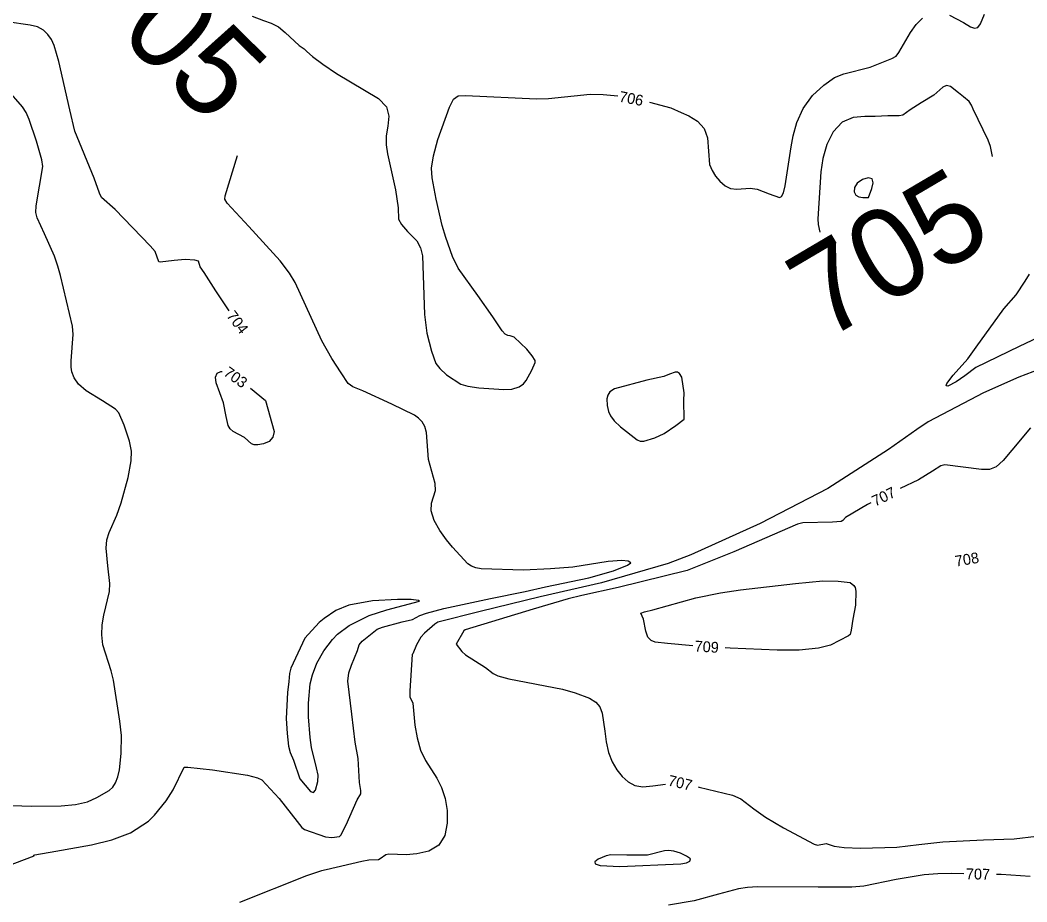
# Model space of a CAD drawing. Extents: x -291892836 to 2945206, y -477993085 to 1832792.
# Drawn here: x 1852737.2 to 1853109.9, y 543885.5 to 544211.9 of the extents above; entities that cross this region are included whole.
import ezdxf

# ---------------------------------------------------------------- set-up
doc = ezdxf.new("R2010")
doc.units = 0
for name, color, linetype in [('DT_X_Contour_Minor', 7, 'Continuous'), ('DT_X_Terrain_Ground_Line', 7, 'Continuous'), ('Level 19', 7, 'Continuous')]:
    doc.layers.add(name, color=color, linetype=linetype)

msp = doc.modelspace()

# ---------------------------------------------------------------- linework, layer by layer
at = {"layer": 'DT_X_Contour_Minor'}
for points in [[(1853081.32, 544213.75), (1853086.51, 544210.99), (1853089.13, 544209.42), (1853090.5, 544208.94), (1853091.76, 544209.2), (1853092.83, 544210.45), (1853094.24, 544214.1)], [(1852814.6, 544104.26), (1852809.64, 544111.65), (1852805.39, 544118.44), (1852803.82, 544120.6), (1852803.22, 544122.59), (1852801.84, 544122.98), (1852798.27, 544123.22), (1852794.23, 544122.86), (1852789.04, 544122.25), (1852788.6, 544122.45), (1852787.26, 544126.16), (1852785.39, 544128.35), (1852772.45, 544141.76), (1852767.38, 544146.19), (1852766.54, 544147.78), (1852764.59, 544153.4), (1852757.47, 544170.78), (1852755.59, 544178.62), (1852751.55, 544196.61), (1852749.78, 544202.53), (1852748.8, 544204.66), (1852747.5, 544206.59), (1852745.8, 544208.19), (1852743.64, 544209.35), (1852740.98, 544210.01), (1852732.44, 544211.22)], [(1852823.09, 544213.36), (1852827.35, 544211.79), (1852830.1, 544210.79), (1852832.87, 544209.33), (1852835.38, 544207.33), (1852840.48, 544202.47), (1852842.34, 544201.26), (1852843.32, 544200.22), (1852845.48, 544198.36), (1852849.28, 544195.55), (1852854.28, 544192.17), (1852869.83, 544182.87), (1852872.81, 544179.82), (1852873.76, 544176.33), (1852873.4, 544172.62), (1852872.79, 544169.02), (1852872.74, 544165.72), (1852873.25, 544162.36), (1852876.13, 544148.99), (1852877.14, 544142.38), (1852877.34, 544138.22), (1852878.38, 544136.21), (1852880.67, 544133.67)], [(1852970.25, 544181.51), (1852978.1, 544179.42), (1852982, 544177.73), (1852984.82, 544176.41), (1852987.97, 544174.43), (1852990.49, 544171.73), (1852991.65, 544168.31), (1852992.44, 544158.43), (1852993.37, 544156.18), (1852994.68, 544154.16), (1852996.3, 544152.2), (1852998.18, 544150.53), (1853000.27, 544149.51), (1853002.55, 544149.33), (1853007.52, 544149.68), (1853010.11, 544149.24), (1853014.51, 544147.6), (1853018.39, 544146.18), (1853019.14, 544146.55), (1853019.84, 544147.92), (1853020.44, 544150.55), (1853022.68, 544164.94), (1853023.43, 544168.99), (1853024.76, 544173.99), (1853027.08, 544179.2), (1853030.58, 544183.94), (1853034.72, 544187.84), (1853038.77, 544190.59), (1853042.19, 544192.05), (1853051.88, 544194.41), (1853060.01, 544197.65), (1853061.56, 544198.49), (1853062.59, 544199.93), (1853066.8, 544207.28), (1853068.94, 544210.27), (1853071.26, 544212.65)], [(1852774.57, 543940.37), (1852774.74, 543947), (1852774.12, 543952.31), (1852771.81, 543967.5), (1852770.97, 543970.99), (1852767.87, 543980.64), (1852767.51, 543984.27), (1852767.63, 543988.01), (1852768.15, 543991.55), (1852770.33, 544000.35), (1852770.43, 544003.35), (1852769.71, 544009.82), (1852769.04, 544016.42), (1852769.28, 544019.45), (1852770.15, 544022.21), (1852773.07, 544028.67), (1852774.66, 544033.17), (1852777.22, 544042.58), (1852778.29, 544048.76), (1852778.4, 544052.31), (1852777.67, 544056), (1852775.77, 544061.93), (1852773.73, 544066.48), (1852772.48, 544067.81), (1852767.72, 544070.93), (1852761.71, 544074.7), (1852758.79, 544077.12), (1852757.24, 544079.47), (1852756.39, 544081.7), (1852756.09, 544083.41), (1852756.05, 544085.74), (1852756.89, 544095.5), (1852756.59, 544098.53), (1852752.12, 544117.38), (1852751.19, 544120.74), (1852749.9, 544124.46), (1852746.23, 544132.77), (1852743.47, 544138.64), (1852742.99, 544140.63), (1852743.13, 544143.14), (1852745.56, 544157.67), (1852745.27, 544160.19), (1852743.28, 544167.09), (1852740.54, 544175.11), (1852739.42, 544177.66), (1852738.04, 544179.76), (1852732.32, 544186.41)], [(1852880.67, 544133.67), (1852884.1, 544130.11), (1852885.46, 544127.63), (1852886.17, 544124.56), (1852886.43, 544117.37), (1852886.96, 544102.95), (1852887.74, 544095.94), (1852889.47, 544089.37), (1852891.14, 544084.71), (1852892.58, 544082.9), (1852895.01, 544080.54), (1852900.38, 544077.08), (1852902.91, 544076.4), (1852907.06, 544075.79), (1852916.29, 544075.16), (1852919.21, 544075.3), (1852921.96, 544076.11), (1852923.61, 544077.25), (1852924.54, 544078.41), (1852926.72, 544082.24), (1852927.94, 544085.12), (1852927.9, 544085.84), (1852926.8, 544087.56), (1852924.75, 544090.1), (1852920.13, 544094.48), (1852918.6, 544094.97), (1852917.81, 544095.15), (1852916.84, 544095.67), (1852915.62, 544096.88), (1852912.18, 544102.07), (1852906.72, 544109.96), (1852899.37, 544120.06), (1852897.32, 544124.37), (1852894.77, 544131.38), (1852893.43, 544135.9), (1852891.25, 544145.63), (1852889.74, 544153.52), (1852889.56, 544157.08), (1852890.21, 544161.62), (1852891.87, 544167.72), (1852896.12, 544179.6), (1852897.67, 544182.66), (1852899.36, 544183.83), (1852902.1, 544183.95), (1852928.42, 544182.68), (1852932.78, 544182.84), (1852948.24, 544184.44), (1852953.12, 544184.33), (1852958.47, 544183.8)], [(1853097.26, 544161.35), (1853096.44, 544165.12), (1853095.56, 544167.41), (1853090.02, 544178.94), (1853089.47, 544180.4), (1853088.52, 544181.76), (1853086.51, 544183.42), (1853084.58, 544184.94), (1853081.73, 544187.3), (1853080.22, 544187.73), (1853078.81, 544187.09), (1853075.49, 544184.05), (1853070.78, 544181.21), (1853066.73, 544178.64), (1853064.01, 544176.74), (1853062.7, 544176.47), (1853058.47, 544176.41), (1853053.79, 544176.14), (1853049.95, 544176.2), (1853045.6, 544175.78), (1853041.5, 544174.07), (1853038.26, 544170.56), (1853035.93, 544165.8), (1853034.43, 544160.63), (1853033.66, 544155.76), (1853032.53, 544138.33), (1853032.66, 544136.17), (1853033.34, 544133.36)], [(1852858.94, 543970.2), (1852859.95, 543973.07), (1852862.11, 543978.5), (1852862.78, 543980.61), (1852863.81, 543981.96), (1852869.42, 543986.36), (1852871.36, 543987.11), (1852878.65, 543989.07), (1852882.43, 543990.02), (1852885.25, 543991.47), (1852887.64, 543992.37), (1852894.07, 543994.08), (1852911.32, 543997.8), (1852924.25, 544000.41), (1852931.72, 544002.13), (1852947.75, 544005.4), (1852956.92, 544007.98), (1852962.07, 544010.05), (1852963.3, 544011), (1852962.37, 544011.56), (1852959.97, 544011.77), (1852954.88, 544011.49), (1852941.79, 544009.4), (1852933.53, 544008.74), (1852923.56, 544008.25), (1852907.94, 544008.73), (1852905.96, 544009.15), (1852904.27, 544009.78), (1852903.02, 544010.64), (1852897.28, 544016.79), (1852895.02, 544019.51), (1852892.62, 544022.96), (1852890.56, 544026.69), (1852889.43, 544030.18), (1852889.55, 544033), (1852890.97, 544037.73), (1852890.84, 544040.28), (1852888.41, 544049.22), (1852887.66, 544059.27), (1852886.99, 544061.46), (1852886.01, 544063.22), (1852884.76, 544064.58), (1852883.24, 544065.66), (1852874.84, 544069.75), (1852864.11, 544074.63), (1852860.36, 544076.13), (1852858.68, 544077.36), (1852856.12, 544081.28), (1852852.62, 544086.57), (1852848.95, 544093.2), (1852839.04, 544114.74), (1852837, 544118.17), (1852833.47, 544122.75), (1852821.83, 544135.49), (1852813.92, 544144.12), (1852812.97, 544145.54), (1852813.17, 544146.78), (1852817.69, 544161.73)], [(1853051.34, 544146.23), (1853052.59, 544149.53), (1853053.04, 544151.58), (1853052.69, 544153.08), (1853051.16, 544153.45), (1853049.04, 544152.84), (1853047.13, 544151.56), (1853046.1, 544149.95), (1853045.96, 544148.34), (1853046.58, 544147.07), (1853047.78, 544146.4), (1853049.19, 544146.19), (1853051.34, 544146.23)], [(1853123.05, 544098.64), (1853107.12, 544091), (1853091.04, 544083.28), (1853086.94, 544080.22), (1853083.76, 544077.94), (1853080.64, 544076.41), (1853080.05, 544076.47), (1853080.33, 544077.33), (1853082.69, 544080.47), (1853088.03, 544086.52), (1853091.15, 544090.85), (1853101.44, 544104.94), (1853105.94, 544110.12), (1853109.31, 544115.26), (1853110.87, 544117.85)], [(1853117.29, 544083.7), (1853107.02, 544079.68), (1853093.89, 544073.91), (1853088.95, 544071.25), (1853073.4, 544063.18), (1853069.16, 544060.37), (1853058.77, 544052.91), (1853036.28, 544038.46), (1853011.26, 544025.5), (1852985.52, 544013.92), (1852977.12, 544010.66), (1852952.44, 544003.58), (1852929.71, 543998.4), (1852907.57, 543992.92), (1852891.89, 543988.99), (1852890.8, 543988.3), (1852886.96, 543984.97), (1852885.53, 543983.41), (1852883.94, 543980.55), (1852882.61, 543977.29), (1852882.36, 543977.07), (1852881.48, 543963.63), (1852881.51, 543961.33), (1852882.6, 543958.97), (1852883.39, 543950.92), (1852884.19, 543946.17), (1852885.46, 543941.56), (1852887.27, 543937.76), (1852891.44, 543931.31), (1852893.2, 543927.76), (1852894.52, 543923.77), (1852895.29, 543919.33), (1852895.37, 543914.56), (1852894.46, 543910.03), (1852892.22, 543906.41), (1852888.52, 543904.21), (1852884.14, 543903.18), (1852880.09, 543902.91), (1852873.74, 543903.16), (1852872.57, 543902.81), (1852870.53, 543901.41), (1852869.94, 543901), (1852866.27, 543900.84), (1852863.74, 543900.41), (1852850.51, 543897.29), (1852848.82, 543897), (1852843.21, 543895.13), (1852818.44, 543885.17)], [(1852822.48, 544075.68), (1852828.01, 544071.08), (1852831.23, 544059.54), (1852830.83, 544057.46), (1852829.35, 544055.94), (1852827.27, 544055), (1852825.26, 544054.59), (1852823.83, 544054.65), (1852822.93, 544055.04), (1852820.29, 544057.31), (1852816.03, 544059.54), (1852815, 544060.58), (1852814.29, 544061.84), (1852813.47, 544065.15), (1852812.5, 544070.17), (1852809.77, 544077.65), (1852809.57, 544079.72), (1852810.15, 544081.18), (1852811.52, 544081.83), (1852812.07, 544081.74)], [(1852983.04, 544064.15), (1852982.99, 544071.12), (1852983.06, 544073.87), (1852982.25, 544079.69), (1852981.32, 544081.08), (1852980.61, 544081.5), (1852979.74, 544081.6), (1852977.66, 544080.85), (1852975.51, 544079.89), (1852969.18, 544078.55), (1852957.26, 544075.35), (1852955.53, 544074.23), (1852954.76, 544073.08), (1852954.41, 544071.62), (1852954.53, 544069.22), (1852955.1, 544066.93), (1852955.77, 544065.37), (1852957.2, 544063.48), (1852959.43, 544061.31), (1852965.62, 544056.47), (1852966.83, 544056.01), (1852968.1, 544056.03), (1852972.23, 544057.28), (1852975.68, 544058.8), (1852980.02, 544061.8), (1852983.04, 544064.15)], [(1853111.25, 544060.89), (1853104.42, 544052.64), (1853101.16, 544048.79), (1853098.54, 544046.48), (1853096.1, 544045.55), (1853093.2, 544045.53), (1853079.62, 544047.24), (1853078.14, 544046.9), (1853075.05, 544044.89), (1853069.86, 544041.74), (1853063.04, 544038.44)], [(1853052.23, 544033.23), (1853050.97, 544032.61), (1853042.76, 544027.79), (1853041.82, 544026.61), (1853041.17, 544026.28), (1853038.04, 544026.07), (1853026.97, 544025.79), (1853025, 544025.22), (1853001.51, 544015.1), (1852984.15, 544008.11), (1852958.64, 544001.89), (1852945.12, 543998.83), (1852940.16, 543997.62), (1852927.12, 543993.82), (1852901.92, 543986.15), (1852901.46, 543985.81), (1852898.64, 543980.9), (1852900.71, 543978.2), (1852902.13, 543976.97), (1852909.51, 543972.28), (1852912.37, 543970.01), (1852914.08, 543969.19), (1852918.15, 543968.08), (1852938.03, 543964.15), (1852942.66, 543962.89), (1852948.03, 543960.89), (1852950.3, 543959.44), (1852951.82, 543957.61), (1852952.72, 543955.27), (1852953.64, 543948.65), (1852954.15, 543944.66), (1852954.99, 543940.75), (1852956.35, 543937.27), (1852958.11, 543934.28), (1852960.14, 543931.81), (1852962.31, 543929.87), (1852964.8, 543928.58), (1852967.8, 543928.08), (1852971.43, 543928.37), (1852976.16, 543929.06)], [(1852986.23, 543980.3), (1852976.85, 543981.15), (1852972.31, 543981.65), (1852970.82, 543982.24), (1852969.6, 543983.51), (1852968.86, 543985.61), (1852968.05, 543990.14), (1852967, 543992.37), (1852968.43, 543992.82), (1852971.5, 543993.53), (1852987.36, 543998), (1852996.5, 543999.86), (1853003.95, 544001.01), (1853024.28, 544003.32), (1853034.42, 544004.27), (1853040.03, 544004.24), (1853044.58, 544003.73), (1853045.92, 544002.59), (1853046.32, 544001.89), (1853046.58, 544000.5), (1853046.53, 543995.28), (1853045.54, 543990.13), (1853044.85, 543986.09), (1853044.56, 543984.44), (1853043.95, 543983.96), (1853037.18, 543980.44), (1853032.77, 543979.32), (1853025.68, 543978.66), (1853017.47, 543978.58), (1853000.12, 543979.32), (1852998.2, 543979.44)], [(1852836.55, 543943.16), (1852837.17, 543940.7), (1852838.45, 543937.86), (1852840.74, 543931), (1852844.77, 543926.26), (1852845.78, 543925.96), (1852846.56, 543926.8), (1852847.43, 543930.05), (1852847.59, 543932.31), (1852846.99, 543935.07), (1852845.08, 543942.55), (1852844.56, 543946.35), (1852844.01, 543953.95), (1852843.97, 543959.01), (1852844.64, 543966.16), (1852845.42, 543969.51), (1852847.08, 543973.79), (1852849.71, 543978.45), (1852852.92, 543982.6), (1852854.7, 543984.56), (1852859.05, 543987.83), (1852866.49, 543991.44), (1852872.99, 543993.53), (1852885.01, 543996.83), (1852884.72, 543997.04), (1852881.95, 543997.41), (1852876.98, 543997.41), (1852867.66, 543996.93), (1852858.88, 543995.29), (1852854.11, 543993.34), (1852849.76, 543990.42), (1852847.91, 543988.91), (1852842.64, 543983.12), (1852837.39, 543971.99), (1852836.98, 543970.02), (1852836.73, 543967.01), (1852836.2, 543962.98), (1852835.75, 543953.33), (1852836.07, 543947.74), (1852836.55, 543943.16)], [(1852731.62, 543898.41), (1852742.4, 543902.56), (1852742.13, 543902.68), (1852742.62, 543902.91), (1852750.43, 543904.25), (1852763.6, 543906.52), (1852771.16, 543908.45), (1852778.03, 543910.97), (1852784.71, 543915.34), (1852787.01, 543917.58), (1852791.33, 543922.82), (1852793.81, 543926.99), (1852797.88, 543935.29), (1852799.27, 543935.38), (1852808.44, 543934.3), (1852821.4, 543932.34), (1852825.04, 543931.41), (1852826.72, 543930.6), (1852833.07, 543923.69), (1852839.72, 543915.19), (1852841.5, 543912.93), (1852842.54, 543912.27), (1852850.29, 543909.51), (1852852.66, 543909.33), (1852855.42, 543909.65), (1852855.98, 543910.19), (1852857.94, 543913.92), (1852862.01, 543923.18), (1852863.32, 543925.47), (1852863.36, 543926.65), (1852862.83, 543929.65), (1852862.33, 543938.56), (1852861.21, 543944.6), (1852860.03, 543954.98), (1852858.54, 543967.17), (1852858.94, 543970.2)], [(1852730.6, 543921.29), (1852741.39, 543920.94), (1852752.45, 543920.98), (1852757.68, 543921.45), (1852762.13, 543922.47), (1852765.59, 543924.14), (1852770.19, 543926.71), (1852771.5, 543927.9), (1852772.56, 543929.56), (1852773.37, 543931.72), (1852773.95, 543934.33), (1852774.57, 543940.37)], [(1852988.23, 543928.02), (1852988.59, 543927.94), (1853000.92, 543925.02), (1853004.06, 543923.55), (1853008.84, 543919.89), (1853013.19, 543916.78), (1853019.86, 543912.86), (1853031.16, 543906.76), (1853032.4, 543906.46), (1853035.58, 543907.05), (1853038.56, 543906.07), (1853042.28, 543905.53), (1853048.3, 543905.31), (1853061.79, 543905.71), (1853069.92, 543906.69), (1853078.89, 543907.65), (1853093.91, 543908.44), (1853105.22, 543908.84), (1853113.55, 543909.78)], [(1852959.22, 543898.5), (1852981.88, 543899.56), (1852983.88, 543899.96), (1852985.22, 543900.55), (1852985.35, 543901.38), (1852983.98, 543902.41), (1852981.69, 543903.43), (1852979.25, 543904.19), (1852977.3, 543904.49), (1852975.82, 543904.39), (1852969.47, 543902.79), (1852961.87, 543902.79), (1852955.85, 543902.82), (1852954.19, 543902.56), (1852951.17, 543901.22), (1852950.03, 543900.3), (1852950.13, 543899.49), (1852951.95, 543898.97), (1852959.22, 543898.5)], [(1853086.65, 543895.89), (1853082.08, 543896), (1853076.92, 543895.89), (1853071.86, 543895.48), (1853061.57, 543893.7), (1853049.56, 543891.31), (1853045.11, 543890.96), (1853032.67, 543890.87), (1853010.17, 543890.99), (1853006.46, 543890.75), (1853003.13, 543890.28), (1852995.8, 543888.34), (1852986.82, 543885.86), (1852977.23, 543884.3)], [(1853111.14, 543894.87), (1853100.45, 543895.55), (1853098.64, 543895.6)]]:
    msp.add_lwpolyline(points, dxfattribs=at)

# ---------------------------------------------------------------- texts
at = {"layer": 'DT_X_Terrain_Ground_Line'}
for rotation, p in [(315.1268, (1852755.55, 544224.29)), (30.5157, (1853035.13, 544092.88))]:
    msp.add_text('705', height=33, rotation=rotation, dxfattribs=at).set_placement(p)
at = {"layer": 'Level 19'}
for s, rotation, p in [('706', 349.1719, (1852958.73, 544181.72)), ('704', 307.6039, (1852813.4, 544102.34)), ('703', 324.3858, (1852812.22, 544080.63)), ('707', 25.7716, (1853053.77, 544031.75)), ('708', 9.6028, (1853083.67, 544009.54)), ('709', 356.1849, (1852986.83, 543978.2)), ('707', 347.0463, (1852976.81, 543928.59)), ('707', 358.5914, (1853087.34, 543893.87))]:
    msp.add_text(s, height=4, rotation=rotation, dxfattribs=at).set_placement(p)

doc.saveas('drawing.dxf')
